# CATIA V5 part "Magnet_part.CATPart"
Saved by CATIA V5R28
Part number: Magnet_part
Definition: design
Nomenclature: Magnet_part
Source: Unknown
Bounding box of the stored display mesh (mm): x -6.105 to 6.105, y -6.105 to 6.105, z 119.353 to 130.372
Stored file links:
  D:\paraturbo-cad\STEP\Turbocompressor_for_Christophe\Magnet_part.CATPart
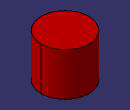
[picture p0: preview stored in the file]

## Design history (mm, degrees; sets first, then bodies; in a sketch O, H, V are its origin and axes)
Body1 "MANIFOLD_SOLID_BREP #941" (main body)
  Solid1: solid without history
